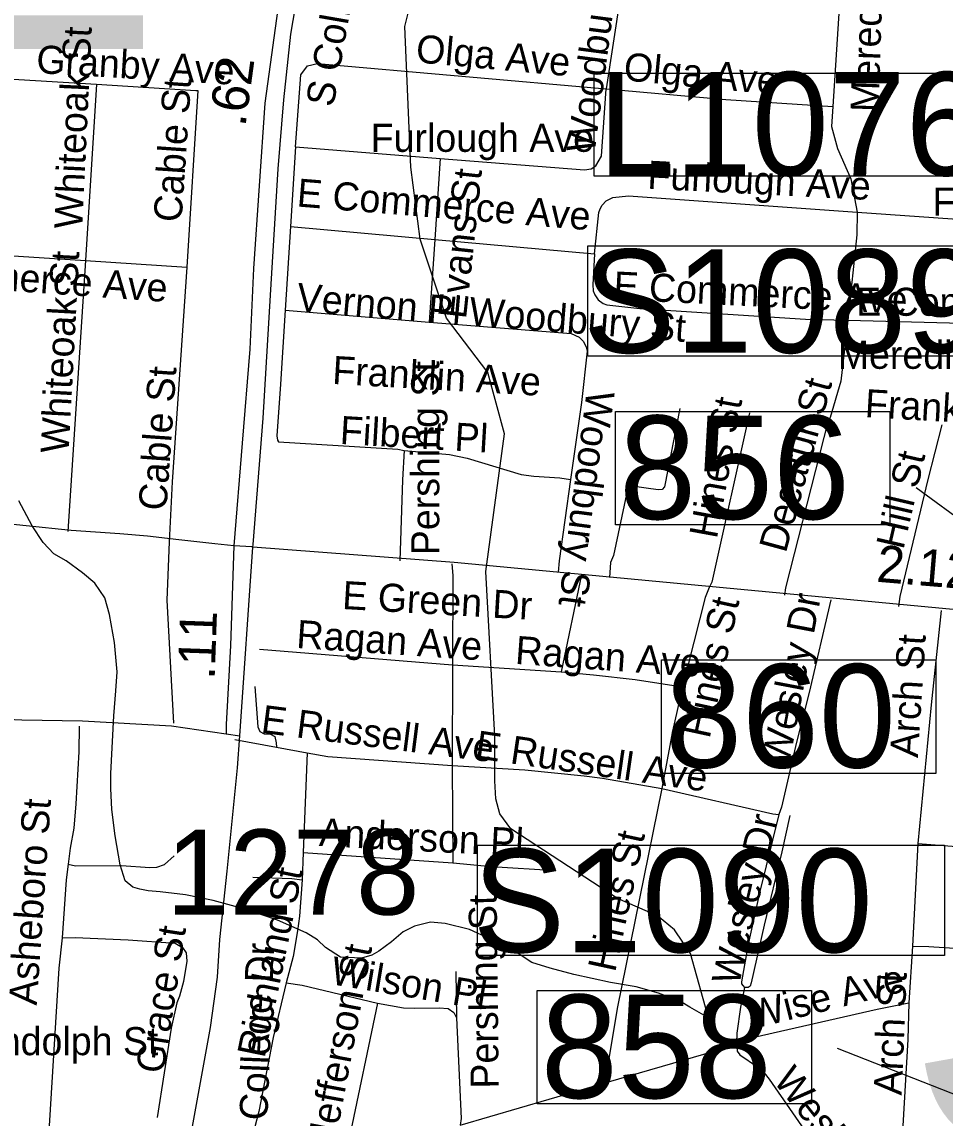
# Model space of a CAD drawing. Extents: x 1662474 to 1856135, y 779280 to 917889.
# Drawn here: x 1705631 to 1708754, y 801612 to 805322 of the extents above; entities that cross this region are included whole.
import ezdxf

# ---------------------------------------------------------------- set-up
doc = ezdxf.new("R2010")
doc.units = 0
for name, color, linetype in [('Cogo Default Point CELL', 7, 'Continuous'), ('Exist Hydrographic Misc Water Feature', 7, 'Continuous'), ('Exist Road Non-System Structure Non-Sys Other Number Label', 7, 'Continuous'), ('Exist Road Non-System Type 51', 7, 'Continuous'), ('Exist Road Non-System Type 51 Label', 7, 'Continuous'), ('Exist Road Primary Interstate Structure Cantilever Sign Number Label', 7, 'Continuous'), ('Exist Road Primary US Structure Ovrhead Sign CELL', 7, 'Continuous'), ('Exist Road Secondary Mileage Tenths English Label', 7, 'Continuous'), ('Exist Road Secondary Type 51 Attributed', 7, 'Continuous'), ('Exist Road Secondary Type 51 Divided Attributed', 7, 'Continuous'), ('Exist Road Secondary Type 51 Label', 7, 'Continuous'), ('Exist Road Secondary Type 51 Undivided 4 Lane Attributed', 7, 'Continuous'), ('Scratch_Level_2', 7, 'Continuous')]:
    doc.layers.add(name, color=color, linetype=linetype)

msp = doc.modelspace()

# ---------------------------------------------------------------- linework, layer by layer
at = {"layer": 'Exist Hydrographic Misc Water Feature'}
for points in [[(1707956.9, 801938.8), (1707892.7, 802168.3), (1707838.7, 802249.2), (1707781.3, 802296.5), (1707646.3, 802354.5), (1707285, 802590.7), (1707247.9, 802641.3), (1707234.4, 802692), (1707231, 802752.7), (1707231, 802904.5), (1707200.6, 803461.3), (1707263, 803927.3), (1707207.1, 804135.2), (1707067.1, 804318.6), (1706978.1, 804586.3), (1706947, 804829.8), (1706926.1, 805306.2), (1706996.1, 805587.1), (1706989.1, 805728.3), (1706964.1, 805771.5)], [(1707961.2, 801946.2), (1707891.1, 801986.6), (1707859, 802006.3), (1707784.3, 802034.6), (1707708.5, 802055.3), (1707622.6, 802070.4), (1707497.8, 802098), (1707417.9, 802118.7), (1707356, 802137.8), (1707282.6, 802186.6), (1707145, 802249.9), (1707063.3, 802270.6), (1707013.3, 802275.1), (1706959.1, 802261.6), (1706920.9, 802242), (1706880.7, 802208.3), (1706838.3, 802176.8), (1706814.2, 802163), (1706780, 802153.2), (1706708.1, 802156), (1706658.4, 802188.5), (1706630.7, 802214.7), (1706592.8, 802239.1), (1706495.2, 802282), (1706389.5, 802317), (1706277.8, 802348), (1706183.9, 802367), (1706098, 802377.8), (1706058, 802380.2), (1706030.1, 802386.4), (1706006.2, 802392.7), (1705980.3, 802414.9), (1705962.8, 802469.1), (1705945.8, 802567.3), (1705934.5, 802655.5), (1705931.3, 802727.5), (1705931.8, 802777.5), (1705941.6, 802973.4), (1705948.4, 803057.5), (1705953, 803121.4), (1705943.9, 803221.5), (1705926.8, 803315.7), (1705911.4, 803371.9), (1705877.8, 803422.2), (1705836.2, 803456.7), (1705780.4, 803497.2), (1705738.7, 803521.6), (1705703.1, 803559.9), (1705665.6, 803616.3), (1705620.5, 803700.7)]]:
    msp.add_lwpolyline(points, dxfattribs=at)
at = {"layer": 'Exist Road Non-System Type 51'}
for p, q in [((1707657.6, 805421.7), (1707607.4, 805094.9)), ((1708396.1, 805367.9), (1708374.4, 805035)), ((1705563.4, 805129.8), (1705883.1, 805110.6)), ((1705883.1, 805110.6), (1705845.5, 804513.8)), ((1706556, 804898.5), (1706539.2, 804629.2)), ((1706556, 804898.5), (1707045.5, 804859.4)), ((1707045.5, 804859.4), (1707027.4, 804585.2)), ((1706539.2, 804629.2), (1706520.9, 804345.5)), ((1706539.2, 804629.2), (1707027.4, 804585.2)), ((1707027.4, 804585.2), (1707009, 804305.7)), ((1707027.4, 804585.2), (1707567.9, 804536.1)), ((1705525.6, 804534.5), (1705845.5, 804513.8)), ((1705845.5, 804513.8), (1705785.9, 803596.5)), ((1705845.5, 804513.8), (1706189.1, 804491.8)), ((1706520.9, 804345.5), (1706505.1, 804095.9)), ((1706520.9, 804345.5), (1707009, 804305.7)), ((1707524.5, 804033.2), (1707486.4, 803772.6)), ((1707524.5, 803451.4), (1707454.9, 803122.2)), ((1706434.5, 803198.1), (1707087.2, 803146.1)), ((1707087.2, 803146.1), (1707086.6, 802804.6)), ((1707087.2, 803146.1), (1707454.9, 803122.2)), ((1706351.2, 802892.6), (1706491.6, 802867.1)), ((1706491.6, 802867.1), (1706595.4, 802847.4)), ((1706595.4, 802847.4), (1706582.8, 802510.9)), ((1707086.6, 802804.6), (1707088.9, 802475.2)), ((1708662.5, 802541.1), (1708643.6, 802192.9)), ((1706582.8, 802510.9), (1706579.4, 802418.5)), ((1706582.8, 802510.9), (1707088.9, 802475.2)), ((1708643.6, 802192.9), (1708631.9, 802002)), ((1707099.4, 802108.1), (1707100.6, 801951.4)), ((1707114, 801587.9), (1707615.1, 801733.8))]:
    msp.add_line(p, q, dxfattribs=at)
for points in [[(1706556, 804898.5), (1706574.9, 805141.9), (1706597.5, 805172.9), (1706630.6, 805180.9), (1707607.4, 805094.9)], [(1705883.1, 805110.6), (1706218.8, 805089.4), (1706226.1, 805088.9), (1706189.1, 804491.8)], [(1707045.5, 804859.4), (1707534.1, 804820.4), (1707557, 804824), (1707572.8, 804834), (1707591.6, 804867.4), (1707607.4, 805094.9)], [(1707607.4, 805094.9), (1708011.9, 805059.4), (1708374.4, 805035)], [(1708374.4, 805035), (1708369.9, 804967.9), (1708390.1, 804893.6), (1708435, 804790.7), (1708456.8, 804677.9)], [(1707567.9, 804536.1), (1707583.2, 804676.2), (1707587, 804689.4), (1707593.5, 804701.4), (1707607.4, 804716.4), (1707630.5, 804727.7), (1707683.6, 804732.4), (1708456.8, 804677.9)], [(1708456.8, 804677.9), (1708455.1, 804600.4), (1708425.5, 804311.7)], [(1708456.8, 804677.9), (1708827.4, 804652.1), (1708984.9, 804651.9)], [(1707567.9, 804536.1), (1707562.6, 804431.9), (1707564.1, 804411.2), (1707568.9, 804398.2), (1707580.4, 804381.2), (1707596.9, 804368.9), (1707610.1, 804363.7), (1707660.8, 804357.9), (1707720.9, 804351.1), (1708281.6, 804315.1), (1708425.5, 804311.7)], [(1706189.1, 804491.8), (1706139.2, 803765.5), (1706128.4, 803562.1)], [(1707009, 804305.7), (1707488.9, 804266.5), (1707515.9, 804254.4), (1707530.5, 804239.8), (1707540, 804221.2), (1707542.9, 804207.2), (1707524.5, 804033.2)], [(1708425.5, 804311.7), (1708401.4, 804105.1), (1708365.1, 803983.1)], [(1708425.5, 804311.7), (1708984.4, 804297.8), (1709146.8, 804288.4)], [(1706505.1, 804095.9), (1706493, 803920.1), (1706495.1, 803906.4), (1706499.4, 803900.9), (1706903, 803875.2), (1706924.2, 803871)], [(1707856.8, 804013.2), (1707804.9, 803748.4), (1707797.4, 803738.8), (1707783.6, 803737.7), (1707694.9, 803750.5), (1707684.4, 803741.9), (1707676.8, 803722.8), (1707632.1, 803516.2), (1707622.4, 803492), (1707619, 803441.1)], [(1708092.1, 803998.4), (1707965.1, 803425.1), (1707955.8, 803407)], [(1708365.1, 803983.1), (1708358.1, 803972.4), (1708214, 803406.2), (1708211.4, 803381.5)], [(1708743.1, 803957.6), (1708696.1, 803773.4), (1708601.4, 803377.1), (1708596.6, 803343.4)], [(1706924.2, 803871), (1706917.9, 803771.8), (1706909.2, 803497.8)], [(1706924.2, 803871), (1707077, 803857.1), (1707136.9, 803844.5), (1707320, 803789.9), (1707362.9, 803783.9), (1707451.2, 803778.6), (1707486.4, 803772.6)], [(1707486.4, 803772.6), (1707448.1, 803497.5), (1707445, 803458.7)], [(1706128.4, 803562.1), (1706120.6, 803364.4), (1706143.6, 802948.2)], [(1707085.1, 803487), (1707088.9, 803448.2), (1707087.2, 803146.1)], [(1707955.8, 803407), (1707942.6, 803373.7), (1707865.9, 803071.5)], [(1708367.8, 803366), (1708294.6, 803051.6), (1708252, 802883.4), (1708200.9, 802663.9), (1708191.9, 802639)], [(1708741, 803329.9), (1708706.9, 803009.9), (1708662.5, 802541.1)], [(1707454.9, 803122.2), (1707564.6, 803112.2), (1707705.1, 803095.7), (1707865.9, 803071.5)], [(1706419, 803072.4), (1706428.8, 802936.1), (1706435.9, 802920.4), (1706450.2, 802912), (1706472, 802910.7), (1706486.4, 802903.6), (1706491.4, 802881.5), (1706491.6, 802867.1)], [(1707865.9, 803071.5), (1707832.4, 802920.7), (1707795.9, 802727.4)], [(1705824.8, 802937.7), (1705823.5, 802851.1), (1705812.8, 802675), (1705805.9, 802592.9), (1705793.9, 802525.6), (1705787, 802470.5)], [(1706595.4, 802847.4), (1706666, 802835.9), (1707086.6, 802804.6)], [(1707086.6, 802804.6), (1707331.9, 802789.9), (1707533.4, 802770.5), (1707594.9, 802762.6), (1707795.9, 802727.4)], [(1707795.9, 802727.4), (1707645, 801982.6), (1707609, 801764.5), (1707615.1, 801733.8)], [(1707795.9, 802727.4), (1708170.9, 802641.1), (1708191.9, 802639)], [(1708191.9, 802639), (1708127.9, 802378.9), (1708088.5, 802199.9), (1708065.1, 802072.6), (1708065.4, 802066.1), (1708069.4, 802060), (1708076.1, 802053.2)], [(1708229.5, 802636.1), (1708201.9, 802512.5), (1708141.6, 802264.5), (1708098.2, 802069.2), (1708094.6, 802057.9), (1708087.5, 802053.4), (1708076.1, 802053.2)], [(1708662.5, 802541.1), (1708852, 802526.4), (1709098.5, 802517.5)], [(1705787, 802470.5), (1705812.4, 802465.8), (1705967.6, 802466.4), (1706063.1, 802459.8), (1706087, 802460.9), (1706112.8, 802469.8), (1706145.5, 802499.1)], [(1705787, 802470.5), (1705780.4, 802417.8), (1705766.8, 802221.2)], [(1707088.9, 802475.2), (1707220, 802463.4), (1707437.4, 802449.2)], [(1706411.6, 802426.7), (1706544.5, 802423), (1706579.4, 802418.5)], [(1706579.4, 802418.5), (1706569.6, 802295.2), (1706562.9, 802245.1), (1706548.4, 802158.2), (1706524.5, 802069.8)], [(1705766.8, 802221.2), (1705756, 802118.9), (1705723.2, 801585.8)], [(1705766.8, 802221.2), (1705811.4, 802222.5), (1705990.4, 802214.6), (1706149.8, 802203.9), (1706173.6, 802188.9), (1706185.9, 802171), (1706188.6, 802143.2), (1706177.9, 802074.4), (1706164.4, 802024.6), (1706155, 802001.8), (1706136.1, 801915.7), (1706088.9, 801613.9)], [(1708643.6, 802192.9), (1708699, 802192), (1709117.9, 802165.2)], [(1706524.5, 802069.8), (1706480.4, 801884.9), (1706431.9, 801634), (1706406.9, 801534.6)], [(1706524.5, 802069.8), (1706579.1, 802061.4), (1706833.6, 802000.9)], [(1708076.1, 802053.2), (1708061.8, 801986.5), (1708049.4, 801898.9), (1708048.9, 801866.6)], [(1706833.6, 802000.9), (1706738.4, 801542.7), (1706729.2, 801511.2)], [(1706833.6, 802000.9), (1706921.6, 801984.9), (1706958.1, 801983.4), (1707042.4, 801985.2), (1707073.4, 801982.1), (1707091.9, 801968.9), (1707100.6, 801951.4)], [(1708048.9, 801866.6), (1708083.2, 801880.2), (1708525, 801980.5), (1708631.9, 802002)], [(1708631.9, 802002), (1708627.9, 801877.4), (1708611.1, 801585.8)], [(1707100.6, 801951.4), (1707116.6, 801610.7), (1707114, 801587.9)], [(1707615.1, 801733.8), (1707938.1, 801828.2), (1708007.4, 801849.5), (1708048.9, 801866.6)], [(1708048.9, 801866.6), (1708051, 801838.5), (1708059.4, 801825.9), (1708119, 801785.2), (1708141.6, 801764.2), (1708158.6, 801743.8), (1708327.1, 801501.2), (1708382.2, 801436.4), (1708468.9, 801355.9), (1708566.5, 801283.1), (1708641.5, 801239.9), (1708711.4, 801207.2), (1708780.1, 801181.2), (1708930.8, 801130.4), (1709096.6, 801064.8), (1709154.1, 801047.7), (1709211.1, 801035.6), (1709308.1, 801025.9), (1709398.8, 801021.8)]]:
    msp.add_lwpolyline(points, dxfattribs=at)
at = {"layer": 'Exist Road Primary Interstate Structure Cantilever Sign Number Label'}
msp.add_lwpolyline([(1707567.4, 805148.6), (1709130.3, 805148.6), (1709130.3, 804799.6), (1707567.4, 804799.6)], close=True, dxfattribs=at)
at = {"layer": 'Exist Road Primary US Structure Ovrhead Sign CELL'}
for points in [[(1707545.7, 804564.1), (1709125.7, 804564.1), (1709125.7, 804190), (1707545.7, 804190)], [(1707172, 802535.6), (1708752, 802535.6), (1708752, 802161.4), (1707172, 802161.4)]]:
    msp.add_lwpolyline(points, close=True, dxfattribs=at)
at = {"layer": 'Exist Road Secondary Type 51 Attributed'}
for points in [[(1706348.1, 803547.9), (1706283.6, 803554.9), (1706161.4, 803569), (1706055.8, 803580.7), (1705962.1, 803589.1), (1705797.9, 803600.4), (1705491.9, 803632.2), (1705181.9, 803668), (1704848.8, 803702.3), (1704701.4, 803705), (1704431.3, 803720.3), (1704053.8, 803729.7), (1703881.9, 803737.7), (1703694.7, 803740.1), (1703601.7, 803736.3)], [(1706412.3, 803544.3), (1706408.7, 803544.6), (1706348.1, 803547.9)], [(1703631.4, 803052.5), (1705631, 802960), (1705835.8, 802956.1), (1706136.8, 802939.6), (1706321.9, 802912.3)], [(1706119.7, 799964.7), (1706129.2, 800449), (1706161.5, 801117.7), (1706190.6, 801444), (1706207.7, 801583), (1706268.7, 801917.7), (1706292.3, 802088.1), (1706300.8, 802216), (1706325, 802447.3), (1706360, 802796.8), (1706368.3, 802905.4)], [(1706321.9, 802912.3), (1706368.3, 802905.4)]]:
    msp.add_lwpolyline(points, dxfattribs=at)
at = {"layer": 'Exist Road Secondary Type 51 Divided Attributed'}
for points in [[(1706412.3, 803544.3), (1706412.9, 803552.5), (1706447.2, 803980.4), (1706472.2, 804396.4), (1706497.2, 804824.8), (1706516.6, 805057.9), (1706540.5, 805279.8), (1706565.2, 805426.9), (1706582.4, 805517.8), (1706622.7, 805738.6), (1706654.3, 805968.2), (1706682.3, 806159.3), (1706698.1, 806294.2), (1706715.7, 806408.2), (1706742, 806550.1), (1706776.7, 806716.3)], [(1706721, 806706.8), (1706675.3, 806527.3), (1706636.7, 806346.8), (1706589.4, 805970), (1706522.8, 805537.1), (1706505.3, 805432), (1706452.6, 805046.3), (1706414, 804487.2), (1706401.8, 804213.8), (1706376.2, 803896.1), (1706348.1, 803547.9)], [(1706348.1, 803547.9), (1706336.1, 803210.6), (1706321.9, 802943.6), (1706321.9, 802912.3)], [(1706368.3, 802905.4), (1706412.3, 803544.3)]]:
    msp.add_lwpolyline(points, dxfattribs=at)
at = {"layer": 'Exist Road Secondary Type 51 Undivided 4 Lane Attributed'}
msp.add_lwpolyline([(1710985.6, 803675.5), (1710725.9, 803556.2), (1710698, 803547.5), (1710519.2, 803462.1), (1710452.1, 803424), (1710369.6, 803383.1), (1710325.6, 803359.1), (1710289.6, 803341.2), (1710233.6, 803313.2), (1710183.6, 803295.2), (1710171.6, 803287.2), (1710138.7, 803279.3), (1710113.7, 803269.2), (1710086.1, 803264.2), (1709931.9, 803248.2), (1709742.2, 803246.6), (1709331.9, 803280.9), (1707093.6, 803491.7), (1706412.3, 803544.3)], dxfattribs=at)
at = {"layer": 'Scratch_Level_2'}
for p, q in [((1710930.6, 802076.4), (1708656.2, 803744.8)), ((1712142.7, 800374.6), (1708390.3, 801846.8))]:
    msp.add_line(p, q, dxfattribs=at)
for points in [[(1707638.7, 804003.2), (1708567.7, 804003.2), (1708567.7, 803619.1), (1707638.7, 803619.1)], [(1707794.2, 803162.2), (1708723.2, 803162.2), (1708723.2, 802778.1), (1707794.2, 802778.1)], [(1707373.8, 802043.6), (1708302.8, 802043.6), (1708302.8, 801659.5), (1707373.8, 801659.5)]]:
    msp.add_lwpolyline(points, close=True, dxfattribs=at)

# ---------------------------------------------------------------- texts
at = {"layer": 'Cogo Default Point CELL'}
msp.add_text('1278', height=288, dxfattribs=at).set_placement((1706118.9, 802300.3))
at = {"layer": 'Exist Road Non-System Structure Non-Sys Other Number Label'}
for s, p in [('J392', (1703067.2, 805230.2)), ('J422', (1708663.9, 801535.9))]:
    msp.add_text(s, height=1049.86, dxfattribs=at).set_placement(p)
at = {"layer": 'Exist Road Non-System Type 51 Label'}
for s, rotation, p in [('Meredith St', 88.1827, (1708529, 805015.2)), ('Woodbury St', 82.5327, (1707568.2, 804874.2)), ('Whiteoak St', 87.2994, (1705834.7, 804619.3)), ('Olga Ave', 354.7854, (1706961.2, 805185)), ('Granby Ave', 356.5814, (1705677.5, 805148.7)), ('Olga Ave', 354.567, (1707664, 805124.1)), ('Cable St', 86.0708, (1706170.5, 804641.8)), ('Evans St', 83.888, (1707133.2, 804313.9)), ('Furlough Ave', 357.0721, (1707745.6, 804757.3)), ('E Commerce Ave', 355.344, (1706558.8, 804697.1)), ('E Commerce Ave', 355.912, (1705127.4, 804444.4)), ('Whiteoak St', 86.9458, (1705788.6, 803859.8)), ('E Commerce Ave', 357.1516, (1707630.7, 804382.5)), ('Vernon Pl', 355.083, (1706557.6, 804343.7)), ('Woodbury St', 355.5147, (1707141.1, 804295.8)), ('Franklin Ave', 356.7131, (1706679.2, 804096.5)), ('Cable St', 85.9995, (1706119.6, 803665.7)), ('Pershing St', 90, (1707042.9, 803516.7)), ('Decatur St', 74.7603, (1708215.2, 803521.2)), ('Franklin Ave', 356.7192, (1708481.1, 803984.1)), ('Woodbury St', 262.5084, (1707542.1, 804077.7)), ('Hines St', 79.606, (1707981.7, 803569.5)), ('Filbert Pl', 356.6567, (1706704.9, 803893.4)), ('Hill St', 76.9727, (1708613, 803532.7)), ('Hines St', 77.7738, (1707957.1, 802893.2)), ('Wesley Dr', 79.2386, (1708225.4, 802802.3)), ('Ragan Ave', 356.1432, (1706557.4, 803203)), ('Ragan Ave', 355.9071, (1707297.7, 803149.1)), ('Arch St', 86.3113, (1708662.1, 802830)), ('E Russell Ave', 352.7208, (1706436.8, 802915.9)), ('E Russell Ave', 351.7227, (1707160.9, 802829.9)), ('Asheboro St', 86.0428, (1705680.8, 801991.7)), ('Wesley Dr', 76.8982, (1708056.4, 802057.2)), ('Anderson Pl', 357.0296, (1706634.8, 802532.6)), ('Hines St', 77.7738, (1707637.7, 802102.5)), ('Richland St', 78.4464, (1706451.5, 801811.9)), ('Pershing St', 90.6292, (1707244.1, 801711.8)), ('Grace St', 81.1975, (1706109.4, 801758.7)), ('Jefferson St', 79.3468, (1706690.7, 801523.6)), ('Wilson Pl', 350.5323, (1706671.5, 802065.4)), ('Wise Ave', 13.9593, (1708102.9, 801912.4)), ('Arch St', 87.6322, (1708607.4, 801687.5)), ('Wesley Dr', 308.3841, (1708169.8, 801738.2))]:
    msp.add_text(s, height=95, rotation=rotation, dxfattribs=at).set_placement(p)
for s, p in [('Furlough Ave', (1706810.8, 804881.8)), ('Furlough Ave', (1708711.8, 804665.9)), ('E Commerce Ave', (1708453.2, 804326.9)), ('Meredith St', (1708391.1, 804147.4)), ('Randolph St', (1705393.4, 801824.5))]:
    msp.add_text(s, height=95, dxfattribs=at).set_placement(p)
at = {"layer": 'Exist Road Primary Interstate Structure Cantilever Sign Number Label'}
msp.add_text('L1076', height=350, dxfattribs=at).set_placement((1707579.9, 804801.7))
at = {"layer": 'Exist Road Primary US Structure Ovrhead Sign CELL'}
for s, p in [('S1089', (1707529.6, 804201.6)), ('S1090', (1707155.9, 802173))]:
    msp.add_text(s, height=350, dxfattribs=at).set_placement(p)
at = {"layer": 'Exist Road Secondary Mileage Tenths English Label'}
for s, rotation, p in [('.62', 82.2714, (1706386.6, 804964.3)), ('2.12', 355.2314, (1708519.6, 803427.1)), ('.11', 87.9639, (1706282.7, 803094.7))]:
    msp.add_text(s, height=125, rotation=rotation, dxfattribs=at).set_placement(p)
at = {"layer": 'Exist Road Secondary Type 51 Label'}
for s, rotation, p in [('S College Dr', 80.1257, (1706684.5, 805030.8)), ('E Green Dr', 356.6962, (1706712.8, 803334.8)), ('S College Dr', 87.755, (1706456.5, 801483))]:
    msp.add_text(s, height=95, rotation=rotation, dxfattribs=at).set_placement(p)
at = {"layer": 'Scratch_Level_2'}
for s, p in [('856', (1707651.3, 803638.9)), ('860', (1707806.8, 802797.9)), ('858', (1707386.4, 801679.2))]:
    msp.add_text(s, height=350, dxfattribs=at).set_placement(p)

doc.saveas('drawing.dxf')
